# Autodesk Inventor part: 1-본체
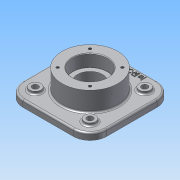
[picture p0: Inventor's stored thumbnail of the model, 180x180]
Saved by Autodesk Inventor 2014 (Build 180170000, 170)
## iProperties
Created: 2015-09
Part Number: 1-본체
Material: 알루미늄 6061
Document SubType Name: Modeling
Designer: study
Mass: 1455.31 g
Surface Area: 796.286 cm^2
Volume: 537.013 cm^3
Density: 2.71 g/cm^3
Appearance: 알루미늄 - 평지
Author: study
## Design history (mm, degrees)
sketch "스케치1"
  geometry: L1 (-75, 75)-(75, 75); L2 (75, 75)-(75, -75); L3 (75, -75)-(-75, -75); L4 (-75, -75)-(-75, 75); L5 (-75, 75)-(75, -75); L6 (75, 75)-(-75, -75); 1 further point
  constraints: 12 end point, 2 midpoint, 2 parallel, 1 horizontal, 1 perpendicular
  dimensions: "d0" = 150 distance of L1.start L1.end; "d1" = 150 distance of L1.end L2.end
extrude "돌출1" new body sketch "스케치1" distance "d2" = 12; taper "d3" = 0 deg
node "작업 평면1"
sketch "스케치2"
  geometry: C1 r 50 at (0, 0); 1 further point
  constraints: 1 centre point, 1 coincident
  dimensions: "d5" = 100 diameter of C1
extrude "돌출2" join sketch "스케치2" distance "d6" = 70; taper "d7" = 0 deg
sketch "스케치3"
  geometry: C1 r 50 at (0, 0) reference; C2 r 10 at (-49, 49); C3 r 10 at (49, 49); C4 r 10 at (-49, -49); C5 r 10 at (49, -49); C6 r 50 at (0, 0) reference
  constraints: 4 centre point, 3 equal radius, 2 horizontal alignment, 2 vertical alignment
  dimensions: "d8" = 20 diameter of C2; "d9" = 98 distance of C5.centre C3.centre; "d10" = 98 distance of C3.centre C2.centre; "d11" = 49 horizontal distance of C1.centre C2.centre; "d12" = 49 horizontal distance of C4.centre C1.centre
extrude "돌출3" join sketch "스케치3" distance "d13" = 5; taper "d14" = 0 deg
sketch "스케치4"
  geometry: C1 r 10 at (0, 0) reference; C2 r 10 at (-98, 0) reference; C3 r 10 at (-98, -98) reference; C4 r 10 at (0, -98) reference; 1 further point
hole "구멍1" sketch "스케치4" at (-98, 0), (0, 0), (0, -98), (-98, -98) diameter "d15" = 11; stored, may be unused: countersink angle "d19" = 90 deg, drill point angle "d21" = 118 deg; dims "d16" = 6, "d17" = 4, "d18" = 2, "d20" = 8
hole "구멍2" diameter "d24" = 45; stored, may be unused: countersink angle "d28" = 90 deg, drill point angle "d30" = 118 deg; dims "d22" = 10, "d23" = 10, "d25" = 6, "d26" = 62, "d27" = 22, "d29" = 8
hole "구멍3" diameter "d33" = 62; stored, may be unused: countersink angle "d37" = 90 deg, drill point angle "d39" = 0 deg; dims "d34" = 6, "d35" = 62, "d36" = 22, "d38" = 22, "d64" = 10, "d65" = 10
sketch "스케치5"
  geometry: L1 (0, 0)-(-41, 0); C1 r 31 at (0, 0) reference; C2 r 50 at (0, 0) reference; A1 r 41 centre (0, 0) between (-28.991, 28.991) and (-41, 0)
  constraints: 2 end point, 2 point on circle, 1 centre point, 1 coincident, 1 horizontal, 1 horizontal alignment
  dimensions: "d40" = 82 diameter of A1; "d42" = 45 deg dimension on C1.centre A1.start L1.end
hole "구멍4" sketch "스케치5" at (-28.991, 28.991) diameter "d43" = 4.917; stored, may be unused: countersink angle "d47" = 90 deg, drill point angle "d49" = 118 deg; dims "d44" = 10, "d45" = 62, "d46" = 22, "d48" = 13
node "작업 평면2"
sketch "스케치6"
  geometry: C1 r 50 at (0, 0) reference; 1 further point
  constraints: 1 vertical alignment, 1 other
  dimensions: "d54" = 65 distance of point (0, 65) C1.centre
feature "엠보싱1" sketch "스케치6" dims "d0" = 150, "d1" = 150, "d55" = 1, "d56" = 0
chamfer "모따기1" distance "d57" = 1; stored, may be unused: second distance "d58" = 2, angle "d59" = 45 deg
fillet "모깎기1" dims "d60" = 30, "d61" = 0.3, "d62" = 3
fillet "모깎기2" dims "d63" = 3
node "솔리드1"
pattern_circular "원형 패턴1" dims angle "d51" = 360 deg
mirror "대칭1"
node "투영된 루프1"
node "투영된 루프2"
node "투영된 루프3"
node "투영된 루프4"
other parameters: "d4" = -23, "d53" = -35
